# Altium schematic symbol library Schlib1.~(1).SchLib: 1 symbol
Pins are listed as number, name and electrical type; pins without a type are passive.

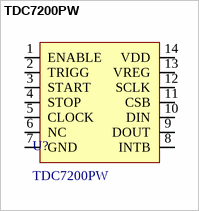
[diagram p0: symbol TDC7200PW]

## TDC7200PW
designator U?
STATIC ULTRASONIC FLOWMETER AF
pins: 1 ENABLE, 2 TRIGG, 3 START, 4 STOP, 5 CLOCK, 6 NC, 7 GND, 8 INTB, 9 DOUT, 10 DIN, 11 CSB, 12 SCLK, 13 VREG, 14 VDD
